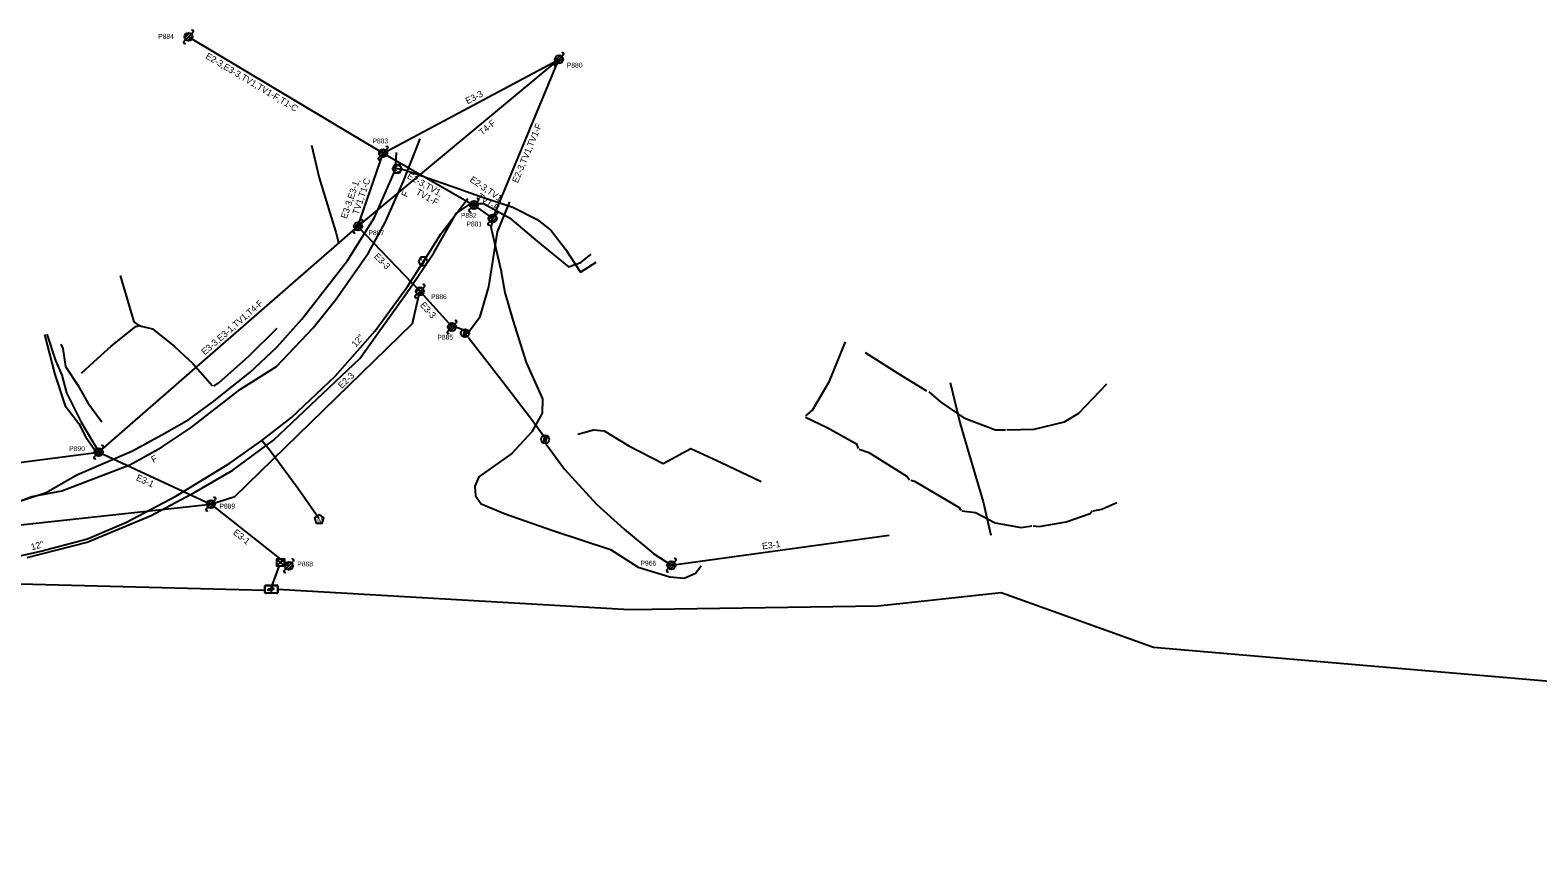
# Model space of a CAD drawing. Extents: x 1614474 to 1865144, y 1098877 to 1212550.
# Drawn here: x 1798607 to 1799537, y 1188245 to 1188751 of the extents above; entities that cross this region are included whole.
import ezdxf

# ---------------------------------------------------------------- set-up
doc = ezdxf.new("R2010")
doc.units = 0
for name, color, linetype in [('BFUSER_CABINET', 7, 'Continuous'), ('BFUSER_DUCTENCLOSURE', 7, 'Continuous'), ('BFUSER_FIBERSPAN', 7, 'Continuous'), ('BFUSER_FIBERSPLICEENCLOSURE', 7, 'Continuous'), ('RD_EX_SU_Elec', 7, 'Continuous'), ('RD_EX_SU_Gas', 7, 'Continuous'), ('RD_EX_SU_H2O', 7, 'Continuous'), ('RD_EX_SU_Ovhd', 7, 'Continuous'), ('RD_EX_SU_Pole', 7, 'Continuous'), ('RD_EX_SU_Telecom', 7, 'Continuous'), ('RD_EX_SU_TX_H2O', 7, 'Continuous'), ('RD_EX_SU_TX_Pole', 7, 'Continuous'), ('RD_EX_SU_TX_Telecom', 7, 'Continuous')]:
    doc.layers.add(name, color=color, linetype=linetype)

# ---------------------------------------------------------------- blocks, each defined once
blk = doc.blocks.new('SUE_GVC')
at = {"layer": 'RD_EX_SU_Gas'}
blk.add_lwpolyline([(1.44, -2.5), (2.89, 0), (1.44, 2.5), (-1.44, 2.5), (-2.89, 0), (-1.44, -2.5)], close=True, dxfattribs=at)
blk.add_text('G', height=3.75, dxfattribs=at).set_placement((-1.34, -1.88))
blk = doc.blocks.new('SUE_ETM')
at = {"layer": 'RD_EX_SU_Elec'}
blk.add_lwpolyline([(1.24, 2.04), (0.23, -1.41), (-0.27, 0.46), (-1.03, -2.36), (-0.34, 1.55), (0.22, -0.39)], close=True, dxfattribs=at)
blk.add_circle((0, 0), 2.55, dxfattribs=at)
blk = doc.blocks.new('SUE_WV')
at = {"layer": 'RD_EX_SU_H2O'}
blk.add_lwpolyline([(2.89, 0), (1.44, 2.5), (-1.44, 2.5), (-2.89, 0), (-1.44, -2.5), (1.44, -2.5)], close=True, dxfattribs=at)
blk.add_text('V', height=3.75, dxfattribs=at).set_placement((-1.43, -1.88))
blk = doc.blocks.new('SUE_WM')
at = {"layer": 'RD_EX_SU_H2O'}
blk.add_lwpolyline([(0, 3.05), (-2.9, 0.94), (-1.79, -2.47), (1.79, -2.47), (2.9, 0.94)], close=True, dxfattribs=at)
blk.add_text('M', height=3.75, dxfattribs=at).set_placement((-1.43, -1.88))

msp = doc.modelspace()

# ---------------------------------------------------------------- linework, layer by layer
at = {"layer": 'BFUSER_CABINET'}
for p, q in [((1798763.7, 1188420.86), (1798758.68, 1188424.84)), ((1798758.7, 1188420.84), (1798763.68, 1188424.86))]:
    msp.add_line(p, q, dxfattribs=at)
msp.add_lwpolyline([(1798763.7, 1188420.86), (1798763.68, 1188424.86), (1798758.68, 1188424.84), (1798758.7, 1188420.84)], close=True, dxfattribs=at)
at = {"layer": 'BFUSER_DUCTENCLOSURE'}
msp.add_line((1798755.41, 1188408.6), (1798755.41, 1188404.09), dxfattribs=at)
for points in [[(1798751.41, 1188404.34), (1798751.41, 1188408.34)], [(1798751.64, 1188404.49), (1798751.64, 1188408.2)], [(1798751.91, 1188408.84), (1798758.91, 1188408.84)], [(1798758.91, 1188403.84), (1798751.91, 1188403.84)], [(1798752.04, 1188408.6), (1798758.77, 1188408.6)], [(1798752.04, 1188404.09), (1798758.77, 1188404.09)], [(1798759.17, 1188408.2), (1798759.17, 1188404.49)], [(1798759.41, 1188408.34), (1798759.41, 1188404.34)]]:
    msp.add_lwpolyline(points, dxfattribs=at)
for centre, radius, start, end in [((1798751.91, 1188408.34), 0.5, 89.99979, 179.99979), ((1798751.91, 1188404.34), 0.5, 179.99979, 269.99979), ((1798752.04, 1188408.2), 0.4, 89.99979, 179.99979), ((1798752.04, 1188404.49), 0.4, 179.99979, 269.99979), ((1798758.77, 1188408.2), 0.4, 359.99979, 89.99979), ((1798758.77, 1188404.49), 0.4, 269.99979, 359.99979), ((1798758.91, 1188408.34), 0.5, 359.99979, 89.99979), ((1798758.91, 1188404.34), 0.5, 269.99979, 359.99979)]:
    msp.add_arc(centre, radius, start, end, dxfattribs=at)
at = {"layer": 'BFUSER_FIBERSPAN'}
msp.add_line((1798756.05, 1188408.68), (1798760.48, 1188420.91), dxfattribs=at)
for points in [[(1795289.89, 1187473.7), (1795592.83, 1187656.19), (1795872.07, 1187807.69), (1796205.63, 1187963.7), (1796468.74, 1188062.74), (1796783.24, 1188163.27), (1797213.26, 1188273.13), (1797596.66, 1188347.09), (1797888.98, 1188382.85), (1798128.96, 1188407.3), (1798504.76, 1188412.2), (1798751.36, 1188405.67)], [(1798759.46, 1188406.4), (1798976.32, 1188393.91), (1799129.62, 1188396.05), (1799205.54, 1188404.27), (1799299.47, 1188370.55), (1800080.43, 1188303.62)]]:
    msp.add_lwpolyline(points, dxfattribs=at)
at = {"layer": 'BFUSER_FIBERSPLICEENCLOSURE'}
for p, q in [((1798753.41, 1188406.3), (1798753.76, 1188406.39)), ((1798753.46, 1188406.14), (1798753.41, 1188406.3)), ((1798753.41, 1188406.28), (1798753.42, 1188406.28)), ((1798753.44, 1188406.16), (1798753.41, 1188406.28)), ((1798753.42, 1188406.28), (1798753.45, 1188406.16)), ((1798753.45, 1188406.16), (1798753.44, 1188406.16)), ((1798753.81, 1188406.24), (1798753.46, 1188406.14)), ((1798753.46, 1188406.07), (1798753.48, 1188406.07)), ((1798753.49, 1188405.95), (1798753.46, 1188406.07)), ((1798753.47, 1188406.09), (1798753.82, 1188406.18)), ((1798753.51, 1188405.93), (1798753.47, 1188406.09)), ((1798753.48, 1188406.07), (1798753.51, 1188405.95)), ((1798753.51, 1188405.95), (1798753.49, 1188405.95)), ((1798753.86, 1188406.03), (1798753.51, 1188405.93)), ((1798753.51, 1188405.88), (1798753.53, 1188405.88)), ((1798753.62, 1188405.49), (1798753.51, 1188405.88)), ((1798753.52, 1188405.9), (1798753.86, 1188405.99)), ((1798753.63, 1188405.48), (1798753.52, 1188405.9)), ((1798753.53, 1188405.88), (1798753.63, 1188405.5)), ((1798753.63, 1188405.5), (1798753.62, 1188405.49)), ((1798753.98, 1188405.57), (1798753.63, 1188405.48)), ((1798753.75, 1188406.54), (1798753.86, 1188406.57)), ((1798754.03, 1188405.51), (1798753.75, 1188406.56)), ((1798754.03, 1188405.52), (1798753.75, 1188406.54)), ((1798753.79, 1188406.23), (1798753.81, 1188406.18)), ((1798753.81, 1188406.72), (1798753.97, 1188406.77)), ((1798754.16, 1188405.43), (1798753.81, 1188406.72)), ((1798753.85, 1188406.02), (1798754.01, 1188405.57)), ((1798753.86, 1188406.57), (1798754.13, 1188405.55)), ((1798753.97, 1188406.77), (1798754.32, 1188405.48)), ((1798754, 1188406.66), (1798756.1, 1188407.23)), ((1798754.01, 1188406.6), (1798756.12, 1188407.16)), ((1798754.13, 1188405.55), (1798754.03, 1188405.52)), ((1798754.32, 1188405.48), (1798754.16, 1188405.43)), ((1798756.72, 1188406.31), (1798754.27, 1188405.65)), ((1798756.74, 1188406.24), (1798754.29, 1188405.58)), ((1798754.38, 1188406.86), (1798754.36, 1188406.85)), ((1798754.36, 1188406.85), (1798754.38, 1188406.77)), ((1798754.4, 1188406.77), (1798754.38, 1188406.86)), ((1798754.38, 1188406.77), (1798754.4, 1188406.77)), ((1798754.69, 1188406.94), (1798754.66, 1188406.94)), ((1798754.66, 1188406.94), (1798754.69, 1188406.85)), ((1798754.71, 1188406.86), (1798754.69, 1188406.94)), ((1798754.69, 1188406.85), (1798754.71, 1188406.86)), ((1798755.47, 1188407.15), (1798755.44, 1188407.15)), ((1798755.44, 1188407.15), (1798755.47, 1188407.06)), ((1798755.49, 1188407.07), (1798755.47, 1188407.15)), ((1798755.47, 1188407.06), (1798755.49, 1188407.07)), ((1798755.78, 1188407.24), (1798755.75, 1188407.23)), ((1798755.75, 1188407.23), (1798755.78, 1188407.14)), ((1798755.8, 1188407.15), (1798755.78, 1188407.24)), ((1798755.78, 1188407.14), (1798755.8, 1188407.15)), ((1798756.12, 1188407.16), (1798756.15, 1188407.04)), ((1798756.19, 1188407.18), (1798756.22, 1188407.05)), ((1798756.3, 1188407.01), (1798756.52, 1188407.06)), ((1798756.32, 1188406.94), (1798756.54, 1188407)), ((1798756.54, 1188407), (1798756.72, 1188406.31)), ((1798756.61, 1188407.01), (1798756.79, 1188406.33))]:
    msp.add_line(p, q, dxfattribs=at)
for centre, radius, start, end in [((1798753.76, 1188406.42), 0.0265, 285.06907, 15.75935), ((1798753.81, 1188406.21), 0.0265, 14.3788, 105.06907), ((1798753.81, 1188406.21), 0.0265, 285.06907, 15.75935), ((1798753.87, 1188406), 0.0265, 14.3788, 105.06907), ((1798753.99, 1188405.55), 0.0265, 14.3788, 105.06907), ((1798756.12, 1188407.16), 0.0694, 15.06907, 105.06907), ((1798756.24, 1188406.81), 0.42, 33.95123, 102.076), ((1798756.29, 1188407.07), 0.139, 195.06907, 285.06907), ((1798756.24, 1188406.81), 0.392, 40.11499, 99.0268), ((1798756.29, 1188407.07), 0.0694, 195.06907, 285.06907), ((1798756.54, 1188407), 0.0694, 15.02072, 105.06907), ((1798755.95, 1188406.46), 0.857, 347.07963, 39.91234), ((1798756.72, 1188406.31), 0.0694, 285.06907, 15.02072)]:
    msp.add_arc(centre, radius, start, end, dxfattribs=at)
at = {"layer": 'RD_EX_SU_Elec'}
for points in [[(1798780.17, 1188680.38), (1798784.99, 1188660.26), (1798791.62, 1188638.66), (1798795.15, 1188626.69), (1798796.83, 1188620.26)], [(1798876.38, 1188564.18), (1798884.32, 1188574.67), (1798889.59, 1188592.86), (1798894.96, 1188626.77), (1798902.46, 1188645.26)], [(1798662.31, 1188599.88), (1798670.56, 1188571.25), (1798673, 1188569.62), (1798675.11, 1188568.6), (1798682.23, 1188567.1), (1798695.74, 1188556.03), (1798706.97, 1188545.7), (1798719.13, 1188531.83)], [(1798638.28, 1188539.58), (1798646, 1188546.74), (1798656.57, 1188556.34), (1798671.95, 1188568.52), (1798674.1, 1188569.09)], [(1798873.14, 1188566.55), (1798870.22, 1188567.72), (1798867.8, 1188568.26)], [(1798615.59, 1188563.41), (1798622.03, 1188538.74), (1798628.38, 1188519.45), (1798636.63, 1188508.68), (1798640.99, 1188500.07), (1798647.8, 1188490.46)], [(1798616.93, 1188563.74), (1798622.27, 1188547.45), (1798626.24, 1188538.38), (1798629.1, 1188527.5), (1798638.14, 1188509.44), (1798649.34, 1188490.72)], [(1798720.06, 1188531.56), (1798723.37, 1188533.93), (1798741.49, 1188550.15), (1798759.07, 1188567.32)], [(1798876.84, 1188561.86), (1798898.52, 1188534.15), (1798915.33, 1188512), (1798923.72, 1188500.49)], [(1799085.07, 1188513.31), (1799089.24, 1188516.9), (1799099.72, 1188534.62), (1799109.56, 1188558.97)], [(1798625.6, 1188557.54), (1798626.96, 1188554.78), (1798628.54, 1188543.82), (1798636.12, 1188532.2), (1798642.28, 1188521.27), (1798650.92, 1188509.69)], [(1799121.68, 1188552.47), (1799141.5, 1188539.82), (1799159.49, 1188528.78)], [(1799174.03, 1188533.97), (1799180.25, 1188508.38), (1799187.88, 1188482.51), (1799194.42, 1188460.36), (1799199.16, 1188439.8)], [(1799209.15, 1188504.77), (1799225.95, 1188505.05), (1799244.6, 1188509.53), (1799253.52, 1188515.01), (1799270.8, 1188533.07)], [(1799160.97, 1188528.03), (1799168.44, 1188521.75), (1799182.61, 1188512.16), (1799202.11, 1188504.66), (1799208.27, 1188504.72)], [(1799084.87, 1188512.55), (1799098.24, 1188506.22), (1799116.26, 1188495.99), (1799117.43, 1188493.07)], [(1798944.42, 1188502), (1798954.24, 1188504.78), (1798960.66, 1188504.09), (1798975.87, 1188494.76), (1798997.16, 1188483.91), (1799014.24, 1188493.21), (1799032.83, 1188484.52), (1799057.5, 1188472.72)], [(1798924.96, 1188495.75), (1798936.35, 1188480.44), (1798956.04, 1188458.79), (1798972.96, 1188443.34), (1798991.39, 1188428.13), (1799001.77, 1188421.4)], [(1799118.01, 1188492.78), (1799123.92, 1188490.69), (1799147.59, 1188475.81), (1799149.1, 1188473.85)], [(1799149.82, 1188473.61), (1799152.17, 1188473.07), (1799179.61, 1188456.86), (1799180.6, 1188455.13)], [(1799262.39, 1188454.73), (1799267.66, 1188455.75), (1799276.83, 1188459.85)], [(1799181.29, 1188454.8), (1799189.81, 1188453.7), (1799201.85, 1188447.27), (1799217.88, 1188444.33), (1799224.47, 1188445.37)], [(1799225.29, 1188445.41), (1799229.11, 1188444.97), (1799245.67, 1188447.98), (1799260.43, 1188453.09), (1799261.7, 1188454.61)]]:
    msp.add_lwpolyline(points, dxfattribs=at)
at = {"layer": 'RD_EX_SU_Gas'}
for points in [[(1798540.02, 1188453.1), (1798561.42, 1188452.55), (1798594.68, 1188458.87), (1798616.68, 1188465.98), (1798635.5, 1188476.83), (1798669.38, 1188491.43), (1798687.92, 1188501.53), (1798704.5, 1188511.11), (1798719.12, 1188521.68), (1798742.22, 1188540.09), (1798758.9, 1188555.78), (1798774.34, 1188572.88), (1798802.43, 1188609.18), (1798819.17, 1188635.67), (1798831.94, 1188665.33), (1798832.73, 1188675.73)], [(1798831.99, 1188666.06), (1798837.68, 1188665.12), (1798870.73, 1188653.66), (1798883.86, 1188648.85), (1798904.3, 1188642), (1798919.36, 1188634.49), (1798927.96, 1188627.75), (1798936.81, 1188616.2), (1798946.04, 1188601.92), (1798955.84, 1188608.11)]]:
    msp.add_lwpolyline(points, dxfattribs=at)
at = {"layer": 'RD_EX_SU_H2O'}
for points in [[(1798784.65, 1188449.98), (1798771.93, 1188468.31), (1798754.82, 1188491.71), (1798749.61, 1188498.15), (1798767.81, 1188512.22), (1798794.77, 1188537.86), (1798819.44, 1188565.79), (1798839.5, 1188593.08), (1798848.61, 1188607.45), (1798860.29, 1188625.84), (1798876.65, 1188647.43)], [(1798395.66, 1188424.19), (1798464.51, 1188422.44), (1798499.05, 1188421.5), (1798554.83, 1188420.73), (1798590.2, 1188424.62), (1798613.36, 1188429.79), (1798642.06, 1188437.41), (1798666.06, 1188447.65), (1798696.65, 1188463.78), (1798729.84, 1188484.09), (1798749.61, 1188498.15)]]:
    msp.add_lwpolyline(points, dxfattribs=at)
at = {"layer": 'RD_EX_SU_Ovhd'}
for p, q in [((1798704.36, 1188747.18), (1798824.36, 1188675.37)), ((1798808.89, 1188630.24), (1798932.85, 1188733.27)), ((1798824.36, 1188675.37), (1798932.85, 1188733.27)), ((1798891.97, 1188635.07), (1798932.85, 1188733.27)), ((1798808.89, 1188630.24), (1798824.36, 1188675.37)), ((1798824.36, 1188675.37), (1798880.4, 1188643.38)), ((1798880.4, 1188643.38), (1798891.97, 1188635.07)), ((1798648.97, 1188490.91), (1798808.89, 1188630.24)), ((1798808.89, 1188630.24), (1798847.07, 1188590.18)), ((1798847.07, 1188590.18), (1798866.91, 1188568.15)), ((1798423.29, 1188461.79), (1798648.97, 1188490.91)), ((1798648.97, 1188490.91), (1798718.12, 1188458.87)), ((1798361.37, 1188420.07), (1798718.12, 1188458.87)), ((1798718.12, 1188458.87), (1798766.24, 1188420.76)), ((1799002.14, 1188421.11), (1799136.58, 1188439.62))]:
    msp.add_line(p, q, dxfattribs=at)
msp.add_lwpolyline([(1798718.12, 1188458.87), (1798732.85, 1188463.58), (1798842.55, 1188570.31), (1798847.07, 1188590.18)], dxfattribs=at)
at = {"layer": 'RD_EX_SU_Pole'}
for p, q in [((1798701.53, 1188744.35), (1798702.59, 1188745.41)), ((1798701.94, 1188746.53), (1798705, 1188749.6)), ((1798702.59, 1188745.41), (1798706.12, 1188748.95)), ((1798703.71, 1188744.77), (1798706.77, 1188747.83)), ((1798706.12, 1188748.95), (1798707.19, 1188750.01)), ((1798930.44, 1188732.62), (1798933.5, 1188735.69)), ((1798934.62, 1188735.04), (1798935.68, 1188736.1)), ((1798930.02, 1188730.44), (1798931.08, 1188731.5)), ((1798931.08, 1188731.5), (1798934.62, 1188735.04)), ((1798932.2, 1188730.86), (1798935.26, 1188733.92)), ((1798821.53, 1188672.54), (1798822.59, 1188673.6)), ((1798821.95, 1188674.72), (1798825.01, 1188677.79)), ((1798822.59, 1188673.6), (1798826.13, 1188677.14)), ((1798823.71, 1188672.96), (1798826.78, 1188676.02)), ((1798826.13, 1188677.14), (1798827.19, 1188678.2)), ((1798877.99, 1188642.73), (1798881.05, 1188645.79)), ((1798878.63, 1188641.61), (1798882.17, 1188645.15)), ((1798879.75, 1188640.96), (1798882.81, 1188644.03)), ((1798882.17, 1188645.15), (1798883.23, 1188646.21)), ((1798877.57, 1188640.55), (1798878.63, 1188641.61)), ((1798889.15, 1188632.24), (1798890.21, 1188633.31)), ((1798889.56, 1188634.43), (1798892.62, 1188637.49)), ((1798890.21, 1188633.31), (1798893.74, 1188636.84)), ((1798891.33, 1188632.66), (1798894.39, 1188635.72)), ((1798893.74, 1188636.84), (1798894.8, 1188637.9)), ((1798806.06, 1188627.41), (1798807.12, 1188628.47)), ((1798806.47, 1188629.59), (1798809.54, 1188632.66)), ((1798807.12, 1188628.47), (1798810.66, 1188632.01)), ((1798808.24, 1188627.83), (1798811.3, 1188630.89)), ((1798810.66, 1188632.01), (1798811.72, 1188633.07)), ((1798844.24, 1188587.35), (1798845.3, 1188588.41)), ((1798844.66, 1188589.53), (1798847.72, 1188592.59)), ((1798845.3, 1188588.41), (1798848.84, 1188591.95)), ((1798846.42, 1188587.76), (1798849.48, 1188590.83)), ((1798848.84, 1188591.95), (1798849.9, 1188593.01)), ((1798864.49, 1188567.51), (1798867.55, 1188570.57)), ((1798865.14, 1188566.39), (1798868.67, 1188569.92)), ((1798866.26, 1188565.74), (1798869.32, 1188568.8)), ((1798868.67, 1188569.92), (1798869.73, 1188570.98)), ((1798864.08, 1188565.33), (1798865.14, 1188566.39)), ((1798650.74, 1188492.67), (1798651.8, 1188493.74)), ((1798646.14, 1188488.08), (1798647.2, 1188489.14)), ((1798646.56, 1188490.26), (1798649.62, 1188493.32)), ((1798647.2, 1188489.14), (1798650.74, 1188492.67)), ((1798648.32, 1188488.49), (1798651.39, 1188491.55)), ((1798715.29, 1188456.04), (1798716.35, 1188457.1)), ((1798715.7, 1188458.22), (1798718.76, 1188461.29)), ((1798716.35, 1188457.1), (1798719.88, 1188460.64)), ((1798717.47, 1188456.46), (1798720.53, 1188459.52)), ((1798719.88, 1188460.64), (1798720.94, 1188461.7)), ((1798763.83, 1188420.11), (1798766.89, 1188423.17)), ((1798764.48, 1188418.99), (1798768.01, 1188422.53)), ((1798765.6, 1188418.34), (1798768.66, 1188421.41)), ((1798768.01, 1188422.53), (1798769.07, 1188423.59)), ((1798999.31, 1188418.28), (1799000.37, 1188419.34)), ((1798999.73, 1188420.46), (1799002.79, 1188423.52)), ((1799000.37, 1188419.34), (1799003.91, 1188422.88)), ((1799001.49, 1188418.69), (1799004.55, 1188421.76)), ((1799003.91, 1188422.88), (1799004.97, 1188423.94)), ((1798763.42, 1188417.93), (1798764.48, 1188418.99))]:
    msp.add_line(p, q, dxfattribs=at)
for centre in [(1798704.36, 1188747.18), (1798932.85, 1188733.27), (1798824.36, 1188675.37), (1798880.4, 1188643.38), (1798891.97, 1188635.07), (1798808.89, 1188630.24), (1798847.07, 1188590.18), (1798866.91, 1188568.15), (1798648.97, 1188490.91), (1798718.12, 1188458.87), (1798766.24, 1188420.76), (1799002.14, 1188421.11)]:
    msp.add_circle(centre, 2.5, dxfattribs=at)
for centre, start, end in [((1798706.66, 1188750.54), 315, 135), ((1798702.06, 1188743.82), 135, 315), ((1798935.15, 1188736.63), 315, 135), ((1798930.55, 1188729.91), 135, 315), ((1798822.06, 1188672.01), 135, 315), ((1798826.66, 1188678.73), 315, 135), ((1798882.7, 1188646.74), 315, 135), ((1798811.19, 1188633.6), 315, 135), ((1798878.1, 1188640.02), 135, 315), ((1798894.27, 1188638.43), 315, 135), ((1798806.59, 1188626.88), 135, 315), ((1798889.68, 1188631.71), 135, 315), ((1798844.77, 1188586.82), 135, 315), ((1798849.37, 1188593.54), 315, 135), ((1798869.2, 1188571.51), 315, 135), ((1798864.61, 1188564.8), 135, 315), ((1798651.27, 1188494.27), 315, 135), ((1798646.67, 1188487.55), 135, 315), ((1798720.41, 1188462.23), 315, 135), ((1798715.82, 1188455.51), 135, 315), ((1798768.54, 1188424.12), 315, 135), ((1799004.44, 1188424.47), 315, 135), ((1798763.95, 1188417.4), 135, 315), ((1798999.84, 1188417.75), 135, 315)]:
    msp.add_arc(centre, 0.75, start, end, dxfattribs=at)
at = {"layer": 'RD_EX_SU_Telecom'}
for points in [[(1798426.98, 1188456.06), (1798429.11, 1188451.85), (1798433.5, 1188450.35), (1798460.68, 1188450.49), (1798483.53, 1188451.77), (1798520.04, 1188450.56), (1798561.41, 1188448.34), (1798576.32, 1188451.82), (1798607.67, 1188463.55), (1798626.32, 1188467.05), (1798668.2, 1188483.11), (1798687.44, 1188493.71), (1798705.93, 1188506.21), (1798736.47, 1188529.82), (1798758.54, 1188543.67), (1798781.25, 1188567.72), (1798795.21, 1188585.11), (1798815.44, 1188613.84), (1798825.56, 1188632.61), (1798837.05, 1188658.15), (1798847.31, 1188684.3)], [(1798604.92, 1188425.94), (1798641.8, 1188435.36), (1798681.26, 1188451.83), (1798708.72, 1188466.52), (1798731.63, 1188479.82), (1798756.78, 1188498.31), (1798809.98, 1188548.77), (1798840.44, 1188591.23), (1798855.7, 1188613.88), (1798869.49, 1188638.14), (1798878.49, 1188644.4), (1798886.27, 1188644.23), (1798902.35, 1188635.48), (1798919.59, 1188620.84), (1798938.73, 1188605.34), (1798946.31, 1188607.94), (1798952.71, 1188613.12)], [(1798892.05, 1188634.5), (1798890.78, 1188629.69), (1798896.95, 1188603.33), (1798899.37, 1188589.45), (1798904.34, 1188572.3), (1798912.69, 1188546.3), (1798922.78, 1188523.84), (1798922.41, 1188515.05), (1798916.2, 1188503.38), (1798903.69, 1188490.1), (1798883.51, 1188475.73), (1798880.95, 1188469.98), (1798881.41, 1188464.04), (1798884.86, 1188459.01), (1798899.61, 1188452.87), (1798929.12, 1188442.57), (1798964.59, 1188430.89), (1798981.72, 1188420), (1799001.2, 1188413.9), (1799010.07, 1188413.14), (1799017.11, 1188416.19), (1799020.64, 1188420.87)]]:
    msp.add_lwpolyline(points, dxfattribs=at)

# ---------------------------------------------------------------- block references
at = {"layer": 'RD_EX_SU_Elec'}
for p in [(1798874.92, 1188564.34), (1798924.34, 1188498.82)]:
    msp.add_blockref('SUE_ETM', p, dxfattribs=at)
at = {"layer": 'RD_EX_SU_Gas'}
msp.add_blockref('SUE_GVC', (1798833.14, 1188665.74), dxfattribs=at)
at = {"layer": 'RD_EX_SU_H2O'}
for name, p in [('SUE_WV', (1798849.08, 1188608.63)), ('SUE_WM', (1798784.96, 1188449.5))]:
    msp.add_blockref(name, p, dxfattribs=at)

# ---------------------------------------------------------------- texts
at = {"layer": 'RD_EX_SU_Ovhd'}
for s, rotation, p in [('E2-3,E3-3,TV1,TV1-F,T1-C', 329.10419, (1798714.46, 1188734.15)), ('E3-3', 28.0886, (1798876.46, 1188705.45)), ('T4-F', 39.73166, (1798885.52, 1188686.13)), ('E2-3,TV1,TV1-F', 67.40015, (1798907.45, 1188656.64)), ('E2-3,TV1,', 330.2777, (1798838.85, 1188660.19)), ('E2-3,TV1,', 325.32661, (1798877.49, 1188658.19)), ('E3-3,E3-1,', 71.07591, (1798801.92, 1188634.58)), ('TV1,T1-C', 71.07591, (1798809.12, 1188637.08)), ('TV1-F', 330.2777, (1798844.2, 1188650.23)), ('TV1-F', 325.32661, (1798881.96, 1188647.8)), ('E3-3', 313.6236, (1798818.49, 1188611.47)), ('E3-3,E3-1,TV1,T4-F', 41.06529, (1798714.43, 1188550.59)), ('E3-3', 312.00661, (1798846.87, 1188581.44)), ('E2-3', 44.21295, (1798798.91, 1188529.86)), ('E3-1', 335.14131, (1798671.66, 1188473.78)), ('E3-1', 321.62406, (1798731.52, 1188440.61)), ('E3-1', 7.84003, (1799058.4, 1188430.87))]:
    msp.add_text(s, height=4, rotation=rotation, dxfattribs=at).set_placement(p)
at = {"layer": 'RD_EX_SU_TX_H2O'}
for rotation, p in [(48.54929, (1798807.56, 1188555.37)), (14.86475, (1798607.78, 1188430.38))]:
    msp.add_text('12"', height=4, rotation=rotation, dxfattribs=at).set_placement(p)
at = {"layer": 'RD_EX_SU_TX_Pole'}
for s, p in [('P884', (1798685.67, 1188745.91)), ('P880', (1798937.69, 1188728.22)), ('P883', (1798817.83, 1188681.41)), ('P882', (1798872.41, 1188635.5)), ('P881', (1798875.79, 1188630.2)), ('P887', (1798815.37, 1188624.78)), ('P886', (1798853.98, 1188585.34)), ('P885', (1798857.86, 1188560.32)), ('P890', (1798630.82, 1188491.56)), ('P889', (1798723.45, 1188456.11)), ('P888', (1798771.47, 1188420.41)), ('P966', (1798983.14, 1188420.93))]:
    msp.add_text(s, height=3, dxfattribs=at).set_placement(p)
at = {"layer": 'RD_EX_SU_TX_Telecom'}
for rotation, p in [(65.78803, (1798839.04, 1188647.95)), (28.87647, (1798682.67, 1188484.23))]:
    msp.add_text('F', height=4, rotation=rotation, dxfattribs=at).set_placement(p)

doc.saveas('drawing.dxf')
